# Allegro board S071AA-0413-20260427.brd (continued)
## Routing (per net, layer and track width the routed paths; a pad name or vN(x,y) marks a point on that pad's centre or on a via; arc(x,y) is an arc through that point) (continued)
S1_DCH110: length 194.3
  L18_DIG w0.076: 141.52,222.61 141.52,220.23 v2(141.12,219.83)
  L18_DIG w0.132: 141.52,222.61 142.3,223.39 142.3,235.5 139.59,238.22 139.59,272.89 146.89,280.2 148.28,280.2 181.91,313.83 181.91,392.46 183.15,393.7
S1_DCH111: length 126.1
  L03_DIG w0.132: v2(141.92,222.23) 143.49,223.8 143.49,261.24 184.49,302.24 184.49,329 185.69,330.2
S1_DCH112: length 198.5
  L18_DIG w0.076: 138.29,216.23 139.92,216.23 v2(140.32,215.83)
  L18_DIG w0.132: 167.91,393.7 166.71,392.5 166.71,318.75 130.33,282.37 130.33,236.8 135.88,231.24 135.88,218.64 138.29,216.23
S1_DCH113: length 189.3
  L20_DIG w0.076: v2(141.12,215.83) 140.72,215.43 138.29,215.43
  L20_DIG w0.132: 138.29,215.43 137.24,215.43 134.85,217.82 134.85,222.67 137.25,225.06 137.25,258.53 197.1,318.39 197.1,372.09 198.39,373.38
S1_DCH114: length 173
  L07_DIG w0.076: v2(139.52,217.43) 139.12,217.83 138.42,217.83 138.29,217.96
  L07_DIG w0.132: 138.29,217.96 136.57,219.69 136.57,224.16 137.29,224.88 137.29,228.42 135.44,230.27 135.44,238.17 132.52,241.1 132.52,258.68 160.86,287.02 160.86,312.96 169.15,321.25 169.15,369.54 170.45,370.84
S1_DCH115: length 129.8
  L03_DIG w0.132: v2(138.72,218.23) 137.37,219.58 137.37,274.82 171.79,309.24 171.79,331.54 172.99,332.74
S1_DCH116: length 194.5
  L18_DIG w0.076: 138.29,217.03 139.92,217.03 v2(140.32,216.63)
  L18_DIG w0.132: 170.45,391.16 169.18,389.89 169.18,315.75 132.45,279.01 132.45,235.35 136.61,231.19 136.61,218.71 138.29,217.03
S1_DCH117: length 195.6
  L18_DIG w0.076: v2(140.32,217.43) 139.92,217.83 138.29,217.83
  L18_DIG w0.132: 172.99,393.7 171.72,392.43 171.72,315.01 134.5,277.8 134.5,234.16 137.19,231.48 137.19,218.94 138.29,217.83
S1_DCH118: length 185.8
  L20_DIG w0.076: v2(141.12,216.63) 140.72,216.23 138.29,216.23
  L20_DIG w0.132: 138.29,216.23 137.74,216.23 135.92,218.06 135.92,222.6 137.85,224.53 137.85,255.82 199.67,317.63 199.67,369.58 200.93,370.84
S1_DCH119: length 228.7
  L22_DIG w0.132: v2(138.72,219.03) 138.15,219.6 138.15,241.84 139.37,243.06 139.37,250 155.69,266.32 205.5,266.32 245.57,306.4 245.57,372.31 246.65,373.38
S1_DCH120: length 175.9
  L07_DIG w0.076: v2(139.52,218.23) 139.12,218.63 138.5,218.63 138.29,218.83
  L07_DIG w0.132: 172.99,373.38 171.81,372.2 171.81,321.38 163.27,312.84 163.27,285.99 145.16,267.89 143.81,267.89 141.86,265.94 140.91,265.94 139.89,264.92 139.89,262.62 134.03,256.75 134.03,241.89 135.89,240.03 135.89,230.38 137.87,228.39 137.87,224.37 137.17,223.67 137.17,219.96 138.29,218.83
S1_DCH121: length 182.5
  L07_DIG w0.076: 148.72,206.68 148.72,208.23 v2(148.32,208.63)
  L07_DIG w0.132: 241.57,76.2 237.32,71.95 232.31,71.95 213.15,91.1 213.15,128.86 149.73,192.28 149.73,205.67 148.72,206.68
S1_DCH122: length 207.4
  L22_DIG w0.132: v2(149.12,207.03) 150.44,205.71 150.44,192.13 207.7,134.87 207.7,72.41 205.23,69.94 169.09,69.94 162.83,76.2
S1_DCH123: length 184.1
  L18_DIG w0.076: 148.72,206.68 148.72,209.03 v2(148.32,209.43)
  L18_DIG w0.132: 175.53,78.74 180.31,83.52 202.87,83.52 210.42,91.08 210.42,132.44 151.2,191.66 151.2,204.2 148.72,206.68
S1_DCH124: length 175.7
  L05_DIG w0.076: 149.52,206.68 149.52,207.43 v2(149.12,207.83)
  L05_DIG w0.132: 185.69,78.74 192.97,86.02 206.54,86.02 214.13,93.62 214.13,129.38 149.93,193.59 149.93,206.27 149.52,206.68
S1_DCH125: length 186
  L18_DIG w0.076: v2(147.52,209.43) 147.92,209.03 147.92,206.68
  L18_DIG w0.132: 147.92,206.68 150.15,204.45 150.15,189.94 208.64,131.44 208.64,92.79 202.01,86.16 177.87,86.16 170.45,78.74
S1_DCH126: length 130.2
  L03_DIG w0.132: v2(148.32,207.03) 149.91,205.44 149.91,189.73 194.54,145.11 194.54,97.75 193.31,96.52
S1_DCH127: length 209.1
  L24_DIG w0.076: v2(148.32,207.83) 148.72,207.43 148.72,206.68
  L24_DIG w0.132: 148.72,206.68 149.81,205.59 149.81,193.44 199.31,143.94 199.31,117.14 213.58,102.87 213.58,76.36 205.53,68.3 180.33,68.3 170.45,58.42
S1_DCH128: length 187.4
  L18_DIG w0.076: v2(146.72,209.43) 147.12,209.03 147.12,206.68
  L18_DIG w0.132: 165.37,78.74 175.18,88.55 201.12,88.55 206.18,93.61 206.18,131.35 147.12,190.41 147.12,206.68
S1_DCH129: length 192.1
  L07_DIG w0.076: v2(146.72,208.63) 147.12,208.23 147.12,206.68
  L07_DIG w0.132: 246.65,76.2 240.58,70.13 230.15,70.13 210.19,90.1 210.19,129.09 147.12,192.16 147.12,206.68
S1_DCH130: length 209.4
  L24_DIG w0.076: v2(146.72,207.83) 147.12,207.43 147.12,206.68
  L24_DIG w0.132: 165.37,58.42 178.13,71.18 203.69,71.18 210.39,77.87 210.39,101.54 196.12,115.81 196.12,143.98 147.12,192.98 147.12,206.68
S1_DCH131: length 198.8
  L22_DIG w0.076: v2(147.52,207.83) 147.92,207.43 147.92,206.68
  L22_DIG w0.132: 167.91,76.2 172.46,71.65 204,71.65 205.54,73.18 205.54,133.97 149.88,189.63 149.88,204.72 147.92,206.68
S1_DCH132: length 185.1
  L20_DIG w0.076: 147.92,206.68 147.92,208.23 v2(147.52,208.63)
  L20_DIG w0.132: 172.99,76.2 174.22,77.43 174.22,82.6 180.04,88.43 202.83,88.43 207.75,93.35 207.75,132.13 149.78,190.1 149.78,204.82 147.92,206.68
S1_DCH133: length 258.3
  L24_DIG w0.076: v2(143.52,221.43) 143.92,221.83 143.92,222.61
  L24_DIG w0.132: 256.81,393.7 255.56,392.45 255.56,296.07 243.87,284.38 241.57,284.38 236.91,279.72 236.91,277.42 217.06,257.57 155.03,257.57 145.53,248.07 145.53,235.67 144.53,234.67 144.53,233.68 145.2,233.01 145.2,232.42 144.44,231.66 144.44,230.76 145.53,229.67 145.53,224.8 143.92,223.19 143.92,222.61
S1_DCH134: length 129.8
  L03_DIG w0.132: v2(143.52,222.23) 145.15,223.86 145.15,230.07 144.48,230.74 144.48,231.88 144.82,232.21 144.82,233.16 144.56,233.42 144.56,234.67 145.15,235.26 145.15,256.97 187.05,298.88 187.05,331.56 188.23,332.74
S1_DCH135: length 195.4
  L18_DIG w0.076: 144.72,222.58 144.72,220.23 v2(144.32,219.83)
  L18_DIG w0.132: 144.72,222.58 145.3,223.16 145.3,229.94 144.48,230.76 144.48,231.85 145.08,232.45 145.08,233.17 144.44,233.81 144.44,234.52 145.87,235.94 145.87,263.83 192.09,310.05 192.09,392.48 193.31,393.7
S1_DCH136: length 205.8
  L20_DIG w0.076: v2(144.32,220.63) 144.72,221.03 144.72,222.61
  L20_DIG w0.132: 269.51,330.2 268.24,328.94 268.24,292.37 239.37,263.5 163.6,263.5 147.5,247.39 147.5,229.63 145.87,228 145.87,223.75 144.72,222.61
S1_DCH137: length 147
  L05_DIG w0.076: 144.72,222.61 144.72,221.83 v2(144.32,221.43)
  L05_DIG w0.132: 144.72,222.61 145.24,223.13 145.24,228.21 143.6,229.85 143.6,235.61 145.24,237.25 145.24,270.82 165.61,291.19 165.61,292.34 176.88,303.61 176.88,351.87 178.07,353.06
S1_DCH138: length 128.3
  L03_DIG w0.132: 190.77,330.2 189.53,328.96 189.53,295.34 147.66,253.47 147.66,250.01 146.07,248.42 146.07,238.43 147.45,237.06 147.45,229.78 146.07,228.4 146.07,223.99 v2(144.32,222.23)
S1_DCH139: length 227.9
  L22_DIG w0.076: 145.52,222.61 145.52,221.83 v2(145.12,221.43)
  L22_DIG w0.132: 254.27,370.84 253.17,369.74 253.17,302.07 240.75,289.64 240.75,286.77 235.25,281.28 235.25,279.72 213.69,258.15 156.89,258.15 147.37,248.63 147.37,224.45 145.52,222.61
S1_DCH140: length 254.6
  L24_DIG w0.132: 259.35,391.16 258.05,389.86 258.05,293.6 235.9,271.44 234.48,271.44 230.9,267.87 230.9,266.45 220.22,255.77 156.13,255.77 147.39,247.03 147.39,224.5 v2(145.12,222.23)
S1_DCH141: length 191.3
  L18_DIG w0.076: 143.92,222.58 143.92,220.23 v2(143.52,219.83)
  L18_DIG w0.132: 143.92,222.58 143.92,224.2 143.48,224.64 143.48,261.63 144.37,262.52 144.37,266.44 170.56,292.63 170.56,293.91 189.49,312.84 189.49,389.88 190.77,391.16
S1_DCH142: length 228.2
  L20_DIG w0.076: v2(143.52,220.63) 143.92,221.03 143.92,222.61
  L20_DIG w0.132: 143.92,222.61 145.12,223.81 145.12,230.12 144.4,230.84 144.4,231.66 145.12,232.37 145.12,233.33 144.49,233.96 144.49,234.64 145.12,235.27 145.12,247.85 164.26,266.99 238.48,266.99 265.78,294.29 265.78,351.87 266.97,353.06
S1_DCH143: length 193.5
  L18_DIG w0.076: 143.12,222.58 143.12,220.23 v2(142.72,219.83)
  L18_DIG w0.132: 188.23,393.7 186.96,392.43 186.96,313.56 165.41,292.01 165.41,291.1 142.2,267.9 142.2,244.48 143.12,243.57 143.12,222.58
S1_DCH144: length 223.7
  L20_DIG w0.076: v2(142.72,220.63) 143.12,221.03 143.12,222.61
  L20_DIG w0.132: 264.43,350.52 263.21,349.31 263.21,293.98 238.82,269.59 164.65,269.59 143.56,248.5 143.56,223.05 143.12,222.61
S1_DCH145: length 229.4
  L22_DIG w0.076: 143.12,222.61 143.12,221.83 v2(142.72,221.43)
  L22_DIG w0.132: 251.73,373.38 250.6,372.26 250.6,302.92 237.13,289.45 237.13,286.73 211.81,261.41 156.64,261.41 143.12,247.89 143.12,222.61
S1_DCH146: length 251.1
  L24_DIG w0.132: 254.27,391.16 253.01,389.9 253.01,298.48 235.61,281.08 233.8,281.08 228.94,276.22 228.94,274.66 215.51,261.23 155.93,261.23 143.4,248.7 143.4,224.2 142.72,223.52 v2(142.72,222.23)
S1_DCH147: length 171.9
  L07_DIG w0.076: 142.32,222.61 142.32,221.03 v2(141.92,220.63)
  L07_DIG w0.132: 142.32,222.61 143.52,223.81 143.52,233.61 145.26,235.35 145.26,250.27 176.97,281.98 176.97,284.84 187.01,294.88 187.01,372.16 188.23,373.38
S1_DCH148: length 143
  L05_DIG w0.076: v2(141.92,221.43) 142.32,221.83 142.32,222.61
  L05_DIG w0.132: 175.53,350.52 174.32,349.32 174.32,303.58 162.73,291.99 162.73,290.89 142.32,270.48 142.32,222.61
S1_DCH149: length 184.7
  L20_DIG w0.076: 149.52,206.68 149.52,208.23 v2(149.12,208.63)
  L20_DIG w0.132: 178.07,76.2 179.42,77.55 179.42,82.54 182.91,86.03 205.39,86.03 210.83,91.47 210.83,132.86 150.4,193.29 150.4,205.8 149.52,206.68
S1_DCH150: length 186.4
  L18_DIG w0.076: 149.52,206.68 149.52,209.03 v2(149.12,209.43)
  L18_DIG w0.132: 149.52,206.68 152.85,203.35 152.85,192.45 211.89,133.41 211.89,100.41 229.52,82.79 250.22,82.79 254.27,78.74
S1_DCH151: length 128.1
  L03_DIG w0.132: 195.85,99.06 197.17,100.38 197.17,146.66 150.42,193.4 150.42,206.52 v2(149.92,207.03)
S1_DCH152: length 207.7
  L24_DIG w0.076: v2(149.92,207.83) 150.32,207.43 150.32,206.68
  L24_DIG w0.132: 175.53,58.42 182.86,65.75 207.33,65.75 215.78,74.2 215.78,103.78 201.51,118.05 201.51,143.76 150.32,194.95 150.32,206.68
S1_DCH153: length 168.3
  L07_DIG w0.076: v2(149.92,208.63) 150.32,208.23 150.32,206.68
  L07_DIG w0.132: 236.49,76.2 215.55,97.14 215.55,129.85 150.32,195.08 150.32,206.68
S1_DCH154: length 189.4
  L18_DIG w0.076: 150.32,206.68 150.32,209.03 v2(149.92,209.43)
  L18_DIG w0.132: 259.35,78.74 253.63,84.46 230.75,84.46 213.84,101.37 213.84,134.09 153.69,194.25 153.69,203.31 150.32,206.68
S1_DCH155: length 189.7
  L22_DIG w0.132: v2(150.72,207.03) 151.14,206.61 151.14,193.73 209.33,135.54 209.33,70.08 206.06,66.82 194.09,66.82 185.69,58.42
S1_DCH156: length 176.6
  L05_DIG w0.076: v2(150.72,207.83) 151.12,207.43 151.12,206.68
  L05_DIG w0.132: 151.12,206.68 151.12,196.56 217.44,130.24 217.44,90.31 210.35,83.22 195.24,83.22 190.77,78.74
S1_DCH157: length 184.9
  L20_DIG w0.076: v2(150.72,208.63) 151.12,208.23 151.12,206.68
  L20_DIG w0.132: 183.15,76.2 184.45,77.5 184.45,82.07 185.85,83.47 208.44,83.47 214.25,89.28 214.25,133.5 151.12,196.64 151.12,206.68
S1_DCH158: length 192.5
  L18_DIG w0.076: 151.12,206.68 151.12,209.03 v2(150.72,209.43)
  L18_DIG w0.132: 151.12,206.68 155.34,202.46 155.34,195.11 215.86,134.58 215.86,102.15 231.64,86.38 256.79,86.38 264.43,78.74
S1_DCH159: length 188.9
  L22_DIG w0.076: 151.92,206.68 151.92,207.43 v2(151.52,207.83)
  L22_DIG w0.132: 151.92,206.68 151.92,203.72 152.65,203 152.65,197.29 211.45,138.48 211.45,68.69 207.51,64.74 197.09,64.74 190.77,58.42
S1_DCH160: length 205.5
  L24_DIG w0.132: 180.61,58.42 185.38,63.19 208.79,63.19 218.23,72.64 218.23,104.79 203.96,119.06 203.96,143.46 152.61,194.81 152.61,205.93 v2(151.52,207.03)
S1_DCH161: length 130.6
  L03_DIG w0.132: 198.39,96.52 199.63,97.76 199.63,150.18 153.73,196.08 153.73,205.62 v2(152.32,207.03)
S1_DCH162: length 185.7
  L24_DIG w0.132: 236.49,55.88 220.38,71.99 220.38,105.68 206.11,119.95 206.11,146.39 155.06,197.43 155.06,205.09 v2(153.12,207.03)
S1_DCH163: length 166.1
  L07_DIG w0.076: v2(151.52,208.63) 151.92,208.23 151.92,206.68
  L07_DIG w0.132: 239.03,78.74 218.99,98.78 218.99,131.28 152.68,197.58 152.68,205.92 151.92,206.68
S1_DCH164: length 187.1
  L22_DIG w0.076: v2(152.32,207.83) 152.72,207.43 152.72,206.68
  L22_DIG w0.132: 152.72,206.68 152.72,204.83 153.7,203.85 153.7,198.7 153.93,198.47 213.56,138.84 213.56,67.62 209.08,63.14 200.57,63.14 195.85,58.42
S1_DCH165: length 206.4
  L18_DIG w0.076: v2(151.52,210.23) 151.92,209.83 154.27,209.83
  L18_DIG w0.132: 274.59,78.74 263.29,90.04 233.59,90.04 220.31,103.32 220.31,152.62 163.1,209.83 154.27,209.83
S1_DCH166: length 194.6
  L24_DIG w0.132: v2(153.92,207.83) 156.25,205.5 161.76,205.5 173.98,193.28 173.98,189.14 208.7,154.43 208.7,121.03 222.97,106.75 222.97,73.45 233.74,62.67 239.1,62.67 240.3,61.47 240.3,57.15 241.57,55.88
S1_DCH167: length 185.2
  L22_DIG w0.076: 153.52,206.68 153.52,207.43 v2(153.12,207.83)
  L22_DIG w0.132: 153.52,206.68 153.52,205.71 155.05,204.18 155.05,199.59 215.86,138.78 215.86,67.24 209.03,60.41 202.92,60.41 200.93,58.42
S1_DCH168: length 195.4
  L18_DIG w0.076: v2(151.52,209.43) 151.92,209.03 151.92,206.68
  L18_DIG w0.132: 269.51,78.74 259.85,88.4 232.83,88.4 218.12,103.11 218.12,134.91 155.92,197.11 155.92,202.68 151.92,206.68
S1_DCH169: length 172.2
  L07_DIG w0.076: v2(152.32,209.43) 152.72,209.03 154.27,209.03
  L07_DIG w0.132: 154.27,209.03 158.73,209.03 222.35,145.41 222.35,100.49 244.11,78.74
S1_DCH170: length 193.8
  L22_DIG w0.076: 154.27,208.23 153.52,208.23 v2(153.12,208.63)
  L22_DIG w0.132: 239.03,58.42 236.19,61.25 231.03,61.25 221.88,70.41 221.88,148.34 185.17,185.04 183.01,185.04 159.82,208.23 154.27,208.23
S1_DCH171: length 183.1
  L05_DIG w0.132: 193.31,76.2 197.63,71.88 205.64,71.88 220.55,86.79 220.55,133.8 155.94,198.41 155.94,205.01 v2(153.92,207.03)
S1_DCH172: length 194.3
  L20_DIG w0.076: v2(152.32,208.63) 152.72,208.23 152.72,206.68
  L20_DIG w0.132: 152.72,206.68 153.74,205.66 153.74,199.24 217.41,135.57 217.41,65.43 206.49,54.52 199.75,54.52 198.39,55.88
S1_DCH173: length 192.9
  L20_DIG w0.076: v2(141.12,214.23) 140.72,213.83 138.29,213.83
  L20_DIG w0.132: 138.29,213.83 135.15,213.83 132.44,216.53 132.44,222.56 135.83,225.94 135.83,231.3 134.8,232.33 134.8,262.76 162.97,290.93 162.97,294.25 192.17,323.45 192.17,372.24 193.31,373.38
S1_DCH174: length 248.9
  L24_DIG w0.076: v2(140.32,214.23) 139.92,214.63 138.29,214.63
  L24_DIG w0.132: 239.03,391.16 237.87,390.01 237.87,322.53 189.46,274.11 147.82,274.11 134.14,260.43 134.14,233.75 135.89,232 135.89,215.92 137.18,214.63 138.29,214.63
S1_DCH175: length 189.3
  L20_DIG w0.076: v2(141.12,215.03) 140.72,214.63 138.29,214.63
  L20_DIG w0.132: 138.29,214.63 135.82,214.63 133.25,217.2 133.25,222.19 136.48,225.42 136.48,232.57 135.67,233.38 135.67,261.79 165.44,291.56 165.44,294.05 194.64,323.25 194.64,369.63 195.85,370.84
S1_DCH176: length 249.4
  L24_DIG w0.076: 138.29,215.43 139.92,215.43 v2(140.32,215.03)
  L24_DIG w0.132: 241.57,393.7 240.46,392.59 240.46,321.95 190.56,272.05 150.58,272.05 135.49,256.96 135.49,233.53 136.54,232.48 136.54,216.4 137.52,215.43 138.29,215.43
S1_DCH177: length 222.9
  L22_DIG w0.076: 138.29,215.43 139.12,215.43 v2(139.52,215.03)
  L22_DIG w0.132: 244.11,370.84 242.97,369.71 242.97,320.93 207.4,285.36 206.57,285.36 202.93,281.72 202.93,280.05 190.7,267.82 154.94,267.82 137.35,250.23 137.35,216.38 138.29,215.43
S1_DCH178: length 134.1
  L03_DIG w0.132: v2(138.72,215.03) 136.36,217.39 136.36,232.59 133.47,235.49 133.47,276.72 166.72,309.97 166.72,331.55 167.91,332.74
S1_DCH179: length 176.5
  L07_DIG w0.076: v2(139.52,215.83) 139.12,216.23 138.29,216.23
  L07_DIG w0.132: 138.29,216.23 135.32,219.21 135.32,225.21 135.84,225.74 135.84,228.19 134.7,229.33 134.7,234 128.54,240.16 128.54,260.85 144.96,277.26 146.35,277.26 149.76,280.68 149.76,282.07 157.73,290.03 157.73,315.03 163.96,321.26 163.96,369.43 165.37,370.84
S1_DCH180: length 151.9
  L05_DIG w0.076: v2(138.72,215.83) 138.29,216.26
  L05_DIG w0.132: 138.29,216.26 136.84,217.71 136.84,232.84 135.55,234.13 135.55,273.06 166.67,304.19 166.67,351.82 167.91,353.06
S1_DCH181: length 133.4
  L03_DIG w0.132: v2(138.72,213.43) 135.86,216.29 135.86,231.44 131.96,235.33 131.96,278.42 164.01,310.47 164.01,328.84 165.37,330.2
S1_DCH182: length 224.2
  L22_DIG w0.076: v2(139.52,213.43) 139.12,213.83 138.29,213.83
  L22_DIG w0.132: 239.03,370.84 237.94,369.76 237.94,322.42 187.46,271.93 154.04,271.93 132.88,250.78 132.88,234.33 135.87,231.34 135.87,216.25 138.29,213.83
S1_DCH183: length 151
  L05_DIG w0.076: 138.29,214.66 v2(138.72,214.23)
  L05_DIG w0.132: 138.29,214.66 135.85,217.1 135.85,232.93 134.31,234.47 134.31,274.73 164.01,304.44 164.01,349.17 165.37,350.52
S1_DCH184: length 226.2
  L22_DIG w0.076: 138.29,214.63 139.12,214.63 v2(139.52,214.23)
  L22_DIG w0.132: 241.57,373.38 240.44,372.25 240.44,322.01 187.81,269.38 153.54,269.38 134.39,250.23 134.39,234.9 136.63,232.66 136.63,216.3 138.29,214.63
S1_DCH185: length 128.4
  L03_DIG w0.132: 200.93,330.2 199.72,328.99 199.72,296.04 198.8,295.12 198.8,284.1 153.55,238.85 153.55,224.26 v2(151.52,222.23)
S1_DCH186: length 239.1
  L20_DIG w0.076: v2(149.12,220.63) 149.52,221.03 149.52,222.61
  L20_DIG w0.132: 149.52,222.61 151.19,224.28 162.94,224.28 176.8,238.14 217.36,238.14 271.53,183.97 271.53,129.83 273.24,128.12 273.24,100.53 274.58,99.18
S1_DCH187: length 262.5
  L24_DIG w0.076: 148.72,222.61 148.72,221.83 v2(148.32,221.43)
  L24_DIG w0.132: 266.97,393.7 265.71,392.44 265.71,293.31 264.62,292.23 264.62,283.88 229.48,248.74 159.33,248.74 149.94,239.35 149.94,223.82 148.72,222.61
S1_DCH188: length 142.8
  L05_DIG w0.132: 185.69,350.52 184.43,349.26 184.43,299.56 152.82,267.94 152.82,224.33 v2(150.72,222.23)
S1_DCH189: length 130.1
  L03_DIG w0.132: 193.31,332.74 192.09,331.52 192.09,296.99 190.93,295.83 190.93,290.81 148,247.89 148,224.31 v2(145.92,222.23)
S1_DCH190: length 143.1
  L05_DIG w0.076: 147.12,222.61 147.12,221.83 v2(146.72,221.43)
  L05_DIG w0.132: 180.61,350.52 179.42,349.33 179.42,300.66 147.95,269.19 147.95,223.44 147.12,222.61
S1_DCH191: length 258.3
  L24_DIG w0.076: v2(145.92,221.43) 146.32,221.83 146.32,222.61
  L24_DIG w0.132: 261.89,393.7 260.65,392.46 260.65,291.54 221.98,252.86 157.04,252.86 148.02,243.85 148.02,224.31 146.32,222.61
S1_DCH192: length 152.1
  L07_DIG w0.076: 146.32,222.61 146.32,221.03 v2(145.92,220.63)
  L07_DIG w0.132: 193.31,353.06 192.13,351.88 192.13,310.64 190.82,309.34 190.82,287.02 148.5,244.69 148.5,225.92 146.32,223.74 146.32,222.61
S1_DCH193: length 169.1
  L07_DIG w0.076: v2(145.12,220.63) 145.52,221.03 145.52,222.61
  L07_DIG w0.132: 190.77,370.84 189.54,369.61 189.54,290.04 147.87,248.37 147.87,227 145.52,224.65 145.52,222.61
S1_DCH194: length 192.3
  L18_DIG w0.076: 145.52,222.58 145.52,220.23 v2(145.12,219.83)
  L18_DIG w0.132: 195.85,391.16 194.62,389.93 194.62,309.78 147.38,262.54 147.38,224.44 145.52,222.58
S1_DCH195: length 151
  L07_DIG w0.076: 150.32,222.61 150.32,221.03 v2(149.92,220.63)
  L07_DIG w0.132: 150.32,222.61 152.73,225.02 152.73,237.97 198.41,283.66 198.41,303.36 199.74,304.68 199.74,349.33 200.93,350.52
S1_DCH196: length 171.5
  L18_DIG w0.076: v2(149.12,219.83) 149.52,220.23 149.52,222.58
  L18_DIG w0.132: 149.52,222.58 151.22,224.28 151.22,238.45 240.28,327.52 240.28,351.77 241.57,353.06
S1_DCH197: length 234.8
  L22_DIG w0.076: v2(149.92,221.43) 150.32,221.83 150.32,222.61
  L22_DIG w0.132: 261.89,373.38 260.77,372.26 260.77,289.84 222.44,251.52 160.18,251.52 151.06,242.39 151.06,223.34 150.32,222.61
S1_DCH198: length 219.5
  L24_DIG w0.132: v2(149.92,222.23) 149.92,222.84 150.99,223.91 150.99,236.45 160.94,246.4 232.15,246.4 268.27,282.53 268.27,349.29 269.51,350.52
S1_DCH199: length 168.8
  L18_DIG w0.076: v2(148.32,219.83) 148.72,220.23 148.72,222.58
  L18_DIG w0.132: 239.03,350.52 237.67,349.16 237.67,327.92 180.84,271.1 179.92,271.1 150.59,241.77 150.59,224.45 148.72,222.58
S1_DCH200: length 196.9
  L18_DIG w0.076: 147.92,222.58 147.92,220.23 v2(147.52,219.83)
  L18_DIG w0.132: 203.4,393.59 202.12,392.31 202.12,307.92 177.05,282.85 177.05,282.15 149.96,255.06 149.96,224.63 147.92,222.58
S1_DCH201: length 230.5
  L22_DIG w0.076: v2(149.12,221.43) 149.52,221.83 149.52,222.61
  L22_DIG w0.132: 149.52,222.61 149.52,223.98 150.09,224.55 150.09,244.7 158.46,253.07 218.9,253.07 258.23,292.4 258.23,369.72 259.35,370.84
S1_DCH202: length 131.2
  L03_DIG w0.132: 198.39,332.74 197.16,331.51 197.16,296.64 195.79,295.27 195.79,285.06 151.09,240.36 151.09,225 v2(148.32,222.23)
S1_DCH203: length 153.2
  L07_DIG w0.076: 148.72,222.61 148.72,221.03 v2(148.32,220.63)
  L07_DIG w0.132: 198.39,353.06 197.15,351.82 197.15,305.27 195.71,303.83 195.71,284.96 150.96,240.21 150.96,224.85 148.72,222.61
S1_DCH204: length 144.9
  L05_DIG w0.132: 183.15,353.06 181.93,351.84 181.93,299.66 149.95,267.68 149.95,223.06 v2(149.12,222.23)
S1_DCH205: length 235.8
  L20_DIG w0.076: v2(150.72,220.63) 151.12,221.03 151.12,222.47 151.26,222.61
  L20_DIG w0.132: 272.16,96.38 270.83,97.71 270.83,127.93 269.07,129.69 269.07,182.19 214.28,236.98 177.95,236.98 164.37,223.41 152.06,223.41 151.26,222.61
S1_DCH206: length 236.6
  L22_DIG w0.132: v2(153.12,222.23) 153.71,222.83 153.71,238.26 161.44,245.99 226.73,245.99 264.72,283.97 264.72,292.14 265.9,293.32 265.9,372.31 266.97,373.38
S1_DCH207: length 175.5
  L18_DIG w0.076: v2(151.52,219.83) 151.92,220.23 154.19,220.23 154.27,220.31
  L18_DIG w0.132: 249.19,350.52 247.92,349.25 247.92,325.83 229.06,306.97 229.06,290.98 161.46,223.38 156.3,223.38 155.04,222.11 155.04,221.07 154.27,220.31
S1_DCH208: length 169.7
  L18_DIG w0.076: v2(149.92,219.83) 150.32,220.23 150.32,222.58
  L18_DIG w0.132: 244.11,350.52 242.91,349.32 242.91,327.55 152.62,237.25 152.62,224.88 150.32,222.58
S1_DCH209: length 222.6
  L24_DIG w0.132: 274.59,350.52 273.29,349.22 273.29,292.15 272.59,291.45 272.59,277.62 237.36,242.39 162.8,242.39 153.67,233.27 153.67,223.58 v2(152.32,222.23)
S1_DCH210: length 224
  L24_DIG w0.076: 151.12,222.61 151.12,221.83 v2(150.72,221.43)
  L24_DIG w0.132: 151.12,222.61 152.62,224.11 152.62,234.97 161.64,243.99 233.55,243.99 270.78,281.23 270.78,351.79 272.05,353.06
S1_DCH211: length 233.6
  L22_DIG w0.076: v2(151.52,221.43) 151.92,221.83 151.92,222.57 151.95,222.61
  L22_DIG w0.132: 151.95,222.61 152.71,223.36 152.71,240.69 160.63,248.61 224.6,248.61 262.14,286.15 262.14,292.65 263.26,293.77 263.26,369.67 264.43,370.84
S1_DCH212: length 153.9
  L07_DIG w0.076: v2(151.52,220.63) 151.92,221.03 151.92,222.61
  L07_DIG w0.132: 203.47,353.06 202.3,351.89 202.3,303.64 201.12,302.45 201.12,282.96 153.66,235.5 153.66,224.35 151.92,222.61
S1_DCH213: length 150.2
  L07_DIG w0.076: 154.27,220.31 154.19,220.23 152.72,220.23 v2(152.32,219.83)
  L07_DIG w0.132: 239.03,330.2 237.75,328.92 237.75,310.78 228.86,301.89 228.86,290.68 161.7,223.52 156.58,223.52 155.12,222.06 155.12,221.16 154.27,220.31
S1_DCH214: length 223.1
  L20_DIG w0.076: 154.27,221.04 154.26,221.03 152.72,221.03 v2(152.32,220.63)
  L20_DIG w0.132: 154.27,221.04 154.39,221.04 155.18,221.83 165.5,221.83 176.27,232.59 213.91,232.59 265.36,181.14 265.36,130.73 268.28,127.81 268.28,99.95 269.25,98.98
S1_DCH215: length 146.5
  L05_DIG w0.076: 152.88,222.61 152.72,222.45 152.72,221.83 v2(152.32,221.43)
  L05_DIG w0.132: 152.88,222.61 154.99,224.72 154.99,267.02 186.97,298.99 186.97,351.8 188.23,353.06
S1_DCH216: length 131
  L03_DIG w0.132: 203.47,332.74 202.25,331.52 202.25,295.86 201.34,294.95 201.34,281.92 155.21,235.79 155.21,223.52 v2(153.92,222.23)
S1_DCH217: length 238.5
  L22_DIG w0.076: v2(153.12,221.43) 153.52,221.03 154.27,221.03
  L22_DIG w0.132: 154.27,221.03 155.47,222.23 155.47,236.71 162.18,243.42 229.91,243.42 268.33,281.84 268.33,369.66 269.51,370.84
S1_DCH218: length 227.7
  L24_DIG w0.132: v2(153.92,221.43) 155.99,223.5 155.99,232.67 164.08,240.77 241,240.77 274.82,274.59 274.82,286.19 275.84,287.21 275.84,351.77 277.13,353.06
S1_DCH219: length 173.6
  L18_DIG w0.076: 151.12,222.58 151.12,220.23 v2(150.72,219.83)
  L18_DIG w0.132: 151.12,222.58 153.55,225.01 153.55,236.06 155.23,237.74 156.39,237.74 245.44,326.79 245.44,351.85 246.65,353.06
S1_DCH220: length 145.9
  L05_DIG w0.076: 154.27,221.03 153.52,221.03 v2(153.12,220.63)
  L05_DIG w0.132: 154.27,221.03 156.02,222.78 156.02,256.5 189.5,289.98 189.5,349.25 190.77,350.52
S1_DCH221: length 236.1
  L22_DIG w0.076: 154.27,220.23 153.52,220.23 v2(153.12,219.83)
  L22_DIG w0.132: 272.05,373.38 270.93,372.26 270.93,280.78 222.84,232.7 171.24,232.7 159.28,220.74 155.63,220.74 155.12,220.23 154.27,220.23
S1_DCH222: length 205.7
  L03_DIG w0.132: 249.19,99.06 250.58,100.45 250.58,185.34 207.03,228.9 169.45,228.9 161.93,221.38 156.27,221.38 v2(153.92,219.03)
S1_DCH223: length 214.3
  L03_DIG w0.132: 251.73,96.52 252.93,97.73 252.93,136.41 254.14,137.61 254.14,186.93 209.87,231.2 169.19,231.2 161.76,223.77 157.06,223.77 v2(153.92,220.63)
S1_DCH224: length 258.9
  L24_DIG w0.132: v2(153.92,219.83) 155.58,221.49 157.26,221.49 160.07,224.3 162.19,224.3 168.7,230.81 208.52,230.81 254.9,184.42 254.9,158.14 273.37,139.67 273.37,59.64 274.59,58.42
S1_DCH225: length 217.4
  L20_DIG w0.076: 154.27,219.43 152.72,219.43 v2(152.32,219.03)
  L20_DIG w0.132: 264.31,99.08 263.25,100.14 263.25,127.91 261.41,129.76 261.41,179.77 209.93,231.25 178.07,231.25 167.63,220.81 155.76,220.81 154.38,219.43 154.27,219.43
S1_DCH226: length 222.2
  L05_DIG w0.076: 154.27,219.43 153.52,219.43 v2(153.12,219.03)
  L05_DIG w0.132: 154.27,219.43 155.16,219.43 156.78,221.05 161.83,221.05 172.35,231.58 214.37,231.58 262.42,183.53 262.42,137.48 263.15,136.75 263.15,97.78 261.89,96.52
S1_DCH227: length 180.3
  L18_DIG w0.076: 154.27,219.52 154.18,219.43 151.92,219.43 v2(151.52,219.03)
  L18_DIG w0.132: 251.73,353.06 250.48,351.81 250.48,324.9 231.52,305.94 231.52,290.98 162.12,221.59 156.33,221.59 154.27,219.52
S1_DCH228: length 180.6
  L18_DIG w0.076: 154.27,218.63 151.92,218.63 v2(151.52,218.23)
  L18_DIG w0.132: 254.27,350.52 252.96,349.21 252.96,323.44 234.18,304.66 234.18,291.13 163.62,220.57 156.21,220.57 154.27,218.63
S1_DCH229: length 188
  L18_DIG w0.076: 154.27,217.83 151.92,217.83 v2(151.52,217.43)
  L18_DIG w0.132: 256.81,353.06 255.54,351.79 255.54,310.23 204.61,259.31 204.61,258.39 163.88,217.65 163.08,217.65 162.55,218.18 161.65,218.18 161.07,217.59 160.28,217.59 158.83,219.04 155.48,219.04 154.27,217.83
S1_DCH230: length 156.5
  L07_DIG w0.076: v2(152.32,217.43) 152.72,217.83 154.27,217.83
  L07_DIG w0.132: 154.27,217.83 155.22,217.83 156.48,219.1 159.38,219.1 160.2,219.92 160.89,219.92 161.71,219.1 162.55,219.1 233.78,290.33 233.78,299.25 242.92,308.38 242.92,329.01 244.11,330.2
S1_DCH231: length 155.4
  L07_DIG w0.076: 154.27,218.63 152.72,218.63 v2(152.32,218.23)
  L07_DIG w0.132: 241.57,332.74 240.37,331.54 240.37,309.82 231.3,300.76 231.3,290.49 161.6,220.78 156.85,220.78 154.7,218.63 154.27,218.63
S1_DCH232: length 218.6
  L05_DIG w0.076: 154.27,217.83 153.52,217.83 v2(153.12,217.43)
  L05_DIG w0.132: 154.27,217.83 156.16,217.83 156.54,218.22 157.37,218.22 158.94,216.65 164.74,216.65 165.58,217.49 165.58,219.91 174.49,228.82 215.02,228.82 260.69,183.15 260.69,100.4 259.35,99.06
S1_DCH233: length 239.1
  L22_DIG w0.076: v2(153.12,218.23) 153.52,218.63 154.27,218.63
  L22_DIG w0.132: 274.59,370.84 273.46,369.71 273.46,297.25 274.74,295.96 274.74,279.89 225.42,230.57 173.79,230.57 163.98,220.77 161.13,220.77 158.99,218.63 154.27,218.63
S1_DCH234: length 255.5
  L24_DIG w0.132: 272.05,55.88 270.9,57.03 270.9,133.48 250.31,154.07 250.31,183.65 206.06,227.89 168.71,227.89 161.12,220.3 160.69,220.3 159.42,219.04 154.73,219.04 v2(153.92,218.23)
S1_DCH235: length 128.3
  L03_DIG w0.132: v2(146.72,222.23) 148.51,224.02 148.51,244.9 193.13,289.52 193.13,295.55 194.55,296.97 194.55,328.9 195.85,330.2
S1_DCH236: length 211.6
  L20_DIG w0.076: v2(147.52,220.63) 147.92,221.03 147.92,222.61
  L20_DIG w0.132: 277.13,332.74 275.94,331.55 275.94,290.22 243,257.27 164.84,257.27 150.1,242.53 150.1,224.79 147.92,222.61
S1_DCH237: length 194.3
  L18_DIG w0.076: v2(146.72,219.83) 147.12,220.23 147.12,222.58
  L18_DIG w0.132: 200.93,391.16 199.65,389.88 199.65,308.75 172.91,282.01 171.95,282.01 148.61,258.67 148.61,224.07 147.12,222.58
S1_DCH238: length 151.2
  L07_DIG w0.076: 147.12,222.61 147.12,221.03 v2(146.72,220.63)
  L07_DIG w0.132: 195.85,350.52 194.59,349.26 194.59,296.7 193.55,295.66 193.55,285.51 177.72,269.68 176.12,269.68 175.05,268.61 175.05,267.01 150.17,242.13 150.17,226.76 147.12,223.7 147.12,222.61
S1_DCH239: length 195.6
  L18_DIG w0.076: v2(145.92,219.83) 146.32,220.23 146.32,222.58
  L18_DIG w0.132: 198.39,393.7 197.12,392.43 197.12,308.99 148.01,259.88 148.01,224.27 146.32,222.58
S1_DCH240: length 231.2
  L22_DIG w0.076: v2(147.52,221.43) 147.92,221.83 147.92,222.61
  L22_DIG w0.132: 256.81,373.38 255.7,372.27 255.7,294.95 238.49,277.74 237.53,277.74 215.67,255.87 158.6,255.87 148.44,245.71 148.44,223.12 147.92,222.61
S1_DCH241: length 174.7
  L05_DIG w0.132: 180.61,78.74 190.8,88.93 202.88,88.93 211.16,97.21 211.16,126.24 146.72,190.68 v2(146.72,207.03)
S1_DCH242: length 208.9
  L20_DIG w0.076: v2(146.72,219.03) 146.31,219.44 146.31,222.45
  L20_DIG w0.132: 146.31,222.45 148.66,224.8 148.66,243.31 163.99,258.64 239.85,258.64 273.38,292.17 273.38,328.99 274.59,330.2
S1_DCH243: length 210.6
  L20_DIG w0.076: v2(145.92,219.03) 145.51,219.44 145.51,222.58
  L20_DIG w0.132: 145.51,222.58 148.08,225.14 148.08,245.01 164.38,261.31 239.98,261.31 270.88,292.2 270.88,331.57 272.05,332.74
S1_DCH244: length 257.1
  L24_DIG w0.132: v2(147.52,222.23) 148.67,223.38 148.67,240.94 159.17,251.44 227.07,251.44 262.06,286.44 262.06,293.08 263.1,294.12 263.1,389.83 264.43,391.16
S1_DCH245: length 143.8
  L03_DIG w0.132: K45.2 209.68,174.46 209.68,87.49 200.93,78.74
S1_DCH246: length 163.7
  L03_DIG w0.132: K46.4 K46.5 175.51,217.92 195.05,217.92 235.37,177.6 235.37,97.64 236.49,96.52
S1_DPS11: length 13.9
  L16_DPS w0.076: v2(148.32,216.63) 148.78,217.09 154.27,217.09
  L16_DPS w0.203: 154.27,217.09 154.73,217.09 155.93,218.29 v1(160.44,218.29)
  BOTTOM w0.152: SH15.1 v1(160.44,218.29)
  vias: v1(202.71,292.12) v1(202.71,288.29) v1(202.71,283.21) v1(202.94,279.15) v1(205.52,279.15) v1(205.76,292.12) v1(205.76,288.29) v1(205.76,283.21) v2(144.32,216.63) v2(144.32,215.83) v2(144.32,213.43) v2(144.32,212.63) v2(145.12,216.63) v2(145.12,215.83) v2(145.12,213.43) v2(147.52,216.63) v2(147.52,215.83) v2(147.52,213.43) v2(148.32,215.83)
S1_DPS12: length 15
  L16_DPS w0.076: 140.7,222.61 140.76,222.54 140.76,218.82 140.99,218.59 141.56,218.59 v2(141.92,218.23)
  L16_DPS w0.203: v1(139.86,230.82) 139.86,223.44 140.7,222.61
  BOTTOM w0.152: SH13.1 v1(139.86,230.82)
  vias: v1(172.23,292.12) v1(172.23,288.29) v1(172.23,283.21) v1(172.46,279.15) v1(175.04,279.15) v1(175.28,292.12) v1(175.28,288.29) v1(175.28,283.21) v2(141.92,217.43) v2(141.92,215.03) v2(141.92,214.23) v2(143.52,219.03) v2(144.32,219.03) v2(147.52,219.03) v2(147.52,210.23) v2(149.92,219.03) v2(150.72,219.03) v2(150.72,212.63) v2(150.72,211.83) v2(150.72,211.03) v2(150.72,210.23) v2(151.52,212.63) v2(151.52,211.83) v2(152.32,212.63) v2(152.32,211.83) v2(155.31,213.36) v2(155.31,212.6) v2(155.31,211.84) v2(155.31,211.07)
S1_DPS13: length 11.3
  L09_DPS w0.076: v2(141.92,211.03) 141.51,211.44 141.51,212.02 141.23,212.31 138.29,212.31
  L09_DPS w0.203: v1(132.52,212.67) 137.93,212.67 138.29,212.31
  BOTTOM w0.152: SH9.1 v1(132.52,212.67)
  vias: v1(45.23,292.12) v1(45.23,288.29) v1(45.23,283.21) v1(45.46,279.15) v1(48.04,279.15) v1(48.28,292.12) v1(48.28,288.29) v1(48.28,283.21) v1(61.97,224.69) v1(61.97,209.45) v2(141.92,210.23) v2(145.12,212.63) v2(145.15,211.84)
S1_DPS14: length 13.7
  L11_DPS w0.076: v2(147.38,211.84) 147.13,211.59 147.13,206.68
  L11_DPS w0.203: 147.13,206.68 147.13,206.02 149.14,204.01 v1(149.14,200.22)
  BOTTOM w0.152: v1(149.14,200.22) SH7.1
  vias: v1(146.83,292.12) v1(146.83,288.29) v1(146.83,283.21) v1(147.06,279.15) v1(149.64,279.15) v1(149.88,292.12) v1(149.88,288.29) v1(149.88,283.21) v2(144.32,210.23) v2(145.12,210.23) v2(147.52,212.63)
S1_DPS21: length 14.8
  L11_DPS w0.076: 156.28,212.2 149.9,212.2 148.54,210.85 148.54,210.45 v2(148.32,210.23)
  L11_DPS w0.203: 156.28,212.2 156.64,212.2 157.11,212.67 v1(160.56,212.67)
  BOTTOM w0.152: SH5.1 v1(160.56,212.67)
  vias: v1(123.97,292.12) v1(123.97,288.29) v1(123.97,283.21) v1(124.2,279.15) v1(126.78,279.15) v1(127.02,292.12) v1(127.02,288.29) v1(127.02,283.21)
S1_DPS22: length 20.2
  L11_DPS w0.076: v2(148.32,213.43) 147.93,213.82 147.36,213.82 147.17,214.01 147.17,222.61
  L11_DPS w0.203: v1(145.14,230.92) 145.14,224.72 147.17,222.7 147.17,222.61
  BOTTOM w0.152: SH11.1 v1(145.14,230.92)
  vias: v1(96.03,292.12) v1(96.03,288.29) v1(96.03,283.21) v1(96.26,279.15) v1(98.84,279.15) v1(99.08,292.12) v1(99.08,288.29) v1(99.08,283.21)
S1_DPS23: length 7.5
  L16_DPS w0.203: v1(183.3,204.99) 181.43,203.12 v1(178.87,203.12)
  BOTTOM w0.152: SH3.1 v1(183.3,204.99)
  BOTTOM w0.305: OSC1.4 v1(176.02,204.19)
  vias: v1(235.73,292.12) v1(235.73,288.29) v1(235.73,283.21) v1(235.96,279.15) v1(238.54,279.15) v1(238.78,292.12) v1(238.78,288.29) v1(238.78,283.21) v2(177.6,202.99)
S1_VCC12A_O_REG: length 35.2
  L03_DIG w0.076: 156.28,212.22 148.72,212.22 v2(148.32,212.63)
  L03_DIG w0.132: 156.28,212.22 158.7,212.22 159.75,213.28 169.54,213.28 171.21,211.6 174.59,211.6 K46.3 K46.6
  BOTTOM w0.305: C2.1 K46.6
S1_XOUT: length 30.2
  TOP w0.152: SITE1.Y12 147.52,206.53 148.3,205.75 170.7,205.75 171.69,204.76 174.85,204.76 K45.3
UDBGND: length 147.5
  L14_5V w0.203: 17.24,15.24 UTL1.A02 ; UTL1.A02 18.05,14.43 ; UTL1.A02 18.05,16.05 ; UTL1.A02 18.86,15.24 ; 104.41,410.67 UTL4.B11 ; UTL4.B11 104.41,412.29 ; UTL4.B11 103.6,411.48 ; UTL4.B11 105.22,411.48 ; UTL3.A02 275.4,414.02 ; UTL3.A02 274.59,413.21 ; UTL3.A02 274.59,414.83 ; UTL3.A02 273.78,414.02 ; 165.37,14.43 UTL2.A02 ; UTL2.A02 166.18,15.24 ; UTL2.A02 164.56,15.24 ; UTL2.A02 165.37,16.05 ; UHC230.B2 53.61,353.46 ; UHC230.B2 55.19,353.46 ; UHC230.B2 55.08,351.99 ; UHC230.B2 53.7,351.96 ; UTL1.A10 38.37,16.05 ; UTL1.A10 38.37,14.43 ; UTL1.A10 37.56,15.24 ; UTL1.A10 39.18,15.24 ; UTL2.A08 180.61,16.05 ; UTL2.A08 179.8,15.24 ; UTL2.A08 181.42,15.24 ; UTL2.A08 180.61,14.43 ; 253.46,414.02 UTL3.A10 ; UTL3.A10 254.27,413.21 ; UTL3.A10 254.27,414.83 ; UTL3.A10 255.08,414.02 ; UTL4.A12 101.87,414.83 ; UTL4.A12 101.87,413.21 ; UTL4.A12 101.06,414.02 ; UTL4.A12 102.68,414.02 ; UTL2.B01 162.83,18.59 ; UTL2.B01 162.83,16.97 ; UTL2.B01 163.64,17.78 ; UTL2.B01 162.02,17.78 ; 178.07,16.97 UTL2.B07 ; UTL2.B07 178.07,18.59 ; UTL2.B07 178.88,17.78 ; UTL2.B07 177.26,17.78 ; 32.48,15.24 UTL1.A08 ; UTL1.A08 34.1,15.24 ; UTL1.A08 33.29,16.05 ; UTL1.A08 33.29,14.43 ; 114.57,410.67 UTL4.B07 ; UTL4.B07 114.57,412.29 ; UTL4.B07 115.38,411.48 ; UTL4.B07 113.76,411.48 ; 30.75,16.97 UTL1.B07 ; UTL1.B07 31.56,17.78 ; UTL1.B07 29.94,17.78 ; UTL1.B07 30.75,18.59 ; 244.11,413.21 UTL3.A14 ; UTL3.A14 244.92,414.02 ; UTL3.A14 243.3,414.02 ; UTL3.A14 244.11,414.83 ; UTL2.A10 186.5,15.24 ; UTL2.A10 185.69,16.05 ; UTL2.A10 184.88,15.24 ; UTL2.A10 185.69,14.43 ; UTL2.A14 195.85,16.05 ; UTL2.A14 195.04,15.24 ; UTL2.A14 195.85,14.43 ; UTL2.A14 196.66,15.24 ; UTL2.A12 190.77,16.05 ; UTL2.A12 189.96,15.24 ; UTL2.A12 190.77,14.43 ; UTL2.A12 191.58,15.24 ; UTL4.A14 96.79,414.83 ; UTL4.A14 95.98,414.02 ; UTL4.A14 96.79,413.21 ; UTL4.A14 97.6,414.02 ; 259.35,413.21 UTL3.A08 ; UTL3.A08 259.35,414.83 ; UTL3.A08 260.16,414.02 ; UTL3.A08 258.54,414.02 ; UHC430.B2 55.27,361.96 ; UHC430.B2 53.68,363.55 ; UHC430.B2 53.74,362.16 ; UHC430.B2 55.27,363.69 ; UTL1.A14 48.53,16.05 ; UTL1.A14 49.34,15.24 ; UTL1.A14 47.72,15.24 ; UTL1.A14 48.53,14.43 ; UTL4.A08 112.03,414.83 ; UTL4.A08 112.03,413.21 ; UTL4.A08 111.22,414.02 ; UTL4.A08 112.84,414.02 ; UHC430.D2 53.64,358.56 ; UHC430.D2 55.17,360.09 ; UHC430.D2 53.68,360.05 ; UHC430.D2 55.29,358.43 ; UTL3.B09 256.81,412.29 ; UTL3.B09 257.62,411.48 ; UTL3.B09 256,411.48 ; UTL3.B09 256.81,410.67 ; 42.64,15.24 UTL1.A12 ; UTL1.A12 43.45,14.43 ; UTL1.A12 43.45,16.05 ; UTL1.A12 44.26,15.24 ; UTL3.A12 250,414.02 ; UTL3.A12 249.19,413.21 ; UTL3.A12 249.19,414.83 ; UTL3.A12 248.38,414.02 ; 127.27,413.21 UTL4.A02 ; UTL4.A02 126.46,414.02 ; UTL4.A02 128.08,414.02 ; UTL4.A02 127.27,414.83 ; UTL3.B01 277.94,411.48 ; UTL3.B01 277.13,410.67 ; UTL3.B01 276.32,411.48 ; UTL3.B01 277.13,412.29 ; UTL1.B09 36.64,17.78 ; UTL1.B09 35.83,16.97 ; UTL1.B09 35.83,18.59 ; UTL1.B09 35.02,17.78 ; UTL1.B13 45.99,18.59 ; UTL1.B13 45.99,16.97 ; UTL1.B13 46.8,17.78 ; UTL1.B13 45.18,17.78 ; UTL4.B09 109.49,412.29 ; UTL4.B09 110.3,411.48 ; UTL4.B09 109.49,410.67 ; UTL4.B09 108.68,411.48 ; UHC230.D2 53.64,348.4 ; UHC230.D2 55.17,348.39 ; UHC230.D2 55.19,349.95 ; UHC230.D2 53.68,349.89 ; 14.7,17.78 UTL1.B01 ; UTL1.B01 16.32,17.78 ; UTL1.B01 15.51,18.59 ; UTL1.B01 15.51,16.97 ; 188.23,16.97 UTL2.B11 ; UTL2.B11 189.04,17.78 ; UTL2.B11 187.42,17.78 ; UTL2.B11 188.23,18.59 ; 106.95,413.21 UTL4.A10 ; UTL4.A10 106.95,414.83 ; UTL4.A10 106.14,414.02 ; UTL4.A10 107.76,414.02 ; 99.33,410.67 UTL4.B13 ; UTL4.B13 100.14,411.48 ; UTL4.B13 99.33,412.29 ; UTL4.B13 98.52,411.48 ; UTL2.B13 194.12,17.78 ; UTL2.B13 193.31,18.59 ; UTL2.B13 192.5,17.78 ; UTL2.B13 193.31,16.97 ; 129,411.48 UTL4.B01 ; UTL4.B01 129.81,412.29 ; UTL4.B01 130.62,411.48 ; UTL4.B01 129.81,410.67 ; UTL1.B11 41.72,17.78 ; UTL1.B11 40.91,18.59 ; UTL1.B11 40.91,16.97 ; UTL1.B11 40.1,17.78 ; UTL3.B11 251.73,412.29 ; UTL3.B11 250.92,411.48 ; UTL3.B11 251.73,410.67 ; UTL3.B11 252.54,411.48 ; UTL3.B13 246.65,412.29 ; UTL3.B13 245.84,411.48 ; UTL3.B13 246.65,410.67 ; UTL3.B13 247.46,411.48 ; 261.89,410.67 UTL3.B07 ; UTL3.B07 261.89,412.29 ; UTL3.B07 262.7,411.48 ; UTL3.B07 261.08,411.48 ; UTL2.B09 183.15,18.59 ; UTL2.B09 183.96,17.78 ; UTL2.B09 182.34,17.78 ; UTL2.B09 183.15,16.97
  vias: v1(15.81,284.99) v1(15.81,282.19) v1(16.83,143.26) v1(16.83,140.46) v1(20.57,297.6) v1(22.88,296.69) v1(69.93,18.16) v1(73.16,21.08) v1(75.39,19.56) v1(75.39,18.16) v1(75.39,16.89) v1(75.39,15.49) v1(85.09,131.99) v1(87.39,131.08) v1(96.54,132.78) v1(191.53,133.52) v1(193.84,132.61) v1(263.16,289.13) v1(265.47,288.22) v1(275.91,285.24) v1(275.91,282.45) v1(277.43,133.1) v1(277.43,130.3)
UT1_UP5V: length 547.5
  TOP w0.305: K42.3 156.23,166.88 R42.2 ; R25.2 33.8,230.12 K25.3 ; R29.2 33.8,237.74 K29.3 ; R24.2 104.66,222.5 K24.3 ; K36.3 140.99,143.51 R36.2 ; K40.3 148.61,143.51 R40.2 ; K39.3 125.75,143.76 R39.2 ; KS3.3 50.82,154.18 LRB4.1 ; KS4.3 50.82,161.8 LRB5.1 ; R32.2 104.66,237.74 K32.3 ; R35.2 118.13,143.76 K35.3 ; R3.2 57.42,184.4 K3.3 ; R28.2 104.66,230.12 K28.3 ; R30.2 57.42,237.74 K30.3 ; R2.2 81.04,184.4 K2.3 ; LRB2.1 36.17,132.91 36.62,133.37 KS1.1 ; R17.2 33.8,214.88 K17.3 ; K14.3 81.04,207.26 R14.2 ; KS2.1 54.91,133.37 54.45,132.91 LRB3.1 ; R21.2 33.8,222.5 K21.3 ; K38.3 148.61,166.88 R38.2 ; R5.2 33.8,199.64 K5.3 ; K18.3 57.42,214.88 R18.2 ; K7.3 57.42,207.26 R7.2 ; R13.2 104.66,199.64 K13.3 ; K37.3 125.75,166.88 R37.2 ; K8.3 57.42,199.64 R8.2 ; K15.3 104.66,207.26 R15.2 ; K31.3 81.04,237.74 R31.2 ; R23.2 81.04,222.5 K23.3 ; R46.2 183.02,212.51 182.51,213.03 K46.1 ; R16.2 33.8,184.4 K16.3 ; K1.3 104.66,184.4 R1.2 ; R4.2 33.8,207.26 K4.3 ; K27.3 81.04,230.12 R27.2 ; K34.3 140.99,166.88 R34.2 ; K45.1 183.32,205.92 183.99,205.24 R45.2 ; R20.2 104.66,214.88 K20.3 ; K43.3 133.37,143.76 R43.2 ; R33.2 118.13,166.88 K33.3 ; R10.2 81.04,192.02 K10.3 ; K44.3 156.23,143.51 R44.2 ; K6.3 33.8,192.02 R6.2 ; K12.3 81.04,199.64 R12.2 ; K19.3 81.04,214.88 R19.2 ; R41.2 133.37,166.88 K41.3 ; K22.3 57.42,222.5 R22.2 ; K9.3 57.42,192.02 R9.2 ; R11.2 104.66,192.02 K11.3 ; R26.2 57.42,230.12 K26.3
  L14_5V w0.203: 102.12,185.83 K1.3 ; K1.3 101.01,186.94 ; K1.3 103.24,186.94 ; K1.3 102.12,188.06 ; K25.3 32.38,232.66 ; K25.3 31.26,231.55 ; K25.3 31.26,233.78 ; K25.3 30.14,232.66 ; 121.38,411.48 UTL4.B04 ; UTL4.B04 123,411.48 ; UTL4.B04 122.19,410.67 ; UTL4.B04 122.19,412.29 ; 172.18,15.24 UTL2.A05 ; UTL2.A05 172.99,16.05 ; UTL2.A05 172.99,14.43 ; UTL2.A05 173.8,15.24 ; K21.3 32.38,225.04 ; K21.3 30.14,225.04 ; K21.3 31.26,226.16 ; K21.3 31.26,223.93 ; K33.3 116.7,164.34 ; K33.3 115.59,165.46 ; K33.3 114.47,164.34 ; K33.3 115.59,163.22 ; K46.1 181.42,213.97 ; K46.1 180.48,213.03 ; K46.1 182.36,213.03 ; K46.1 181.42,212.09 ; 180.48,205.92 K45.1 ; K45.1 181.42,206.86 ; K45.1 182.36,205.92 ; K45.1 181.42,204.98 ; K4.3 32.38,209.8 ; K4.3 31.26,210.92 ; K4.3 31.26,208.69 ; K4.3 30.14,209.8 ; 130.83,163.22 K41.3 ; K41.3 130.83,165.46 ; K41.3 131.94,164.34 ; K41.3 129.71,164.34 ; UTL1.A05 25.67,16.05 ; UTL1.A05 24.86,15.24 ; UTL1.A05 25.67,14.43 ; UTL1.A05 26.48,15.24 ; 22.32,17.78 UTL1.B04 ; UTL1.B04 23.13,16.97 ; UTL1.B04 23.13,18.59 ; UTL1.B04 23.94,17.78 ; 123.21,163.22 K37.3 ; K37.3 122.09,164.34 ; K37.3 123.21,165.46 ; K37.3 124.32,164.34 ; 152.57,140.97 K44.3 ; K44.3 154.8,140.97 ; K44.3 153.69,142.09 ; K44.3 153.69,139.85 ; 138.45,163.22 K34.3 ; K34.3 138.45,165.46 ; K34.3 139.56,164.34 ; K34.3 137.33,164.34 ; 102.12,239.17 K32.3 ; K32.3 103.24,240.28 ; K32.3 102.12,241.4 ; K32.3 101.01,240.28 ; 77.38,209.8 K14.3 ; K14.3 78.5,208.69 ; K14.3 78.5,210.92 ; K14.3 79.62,209.8 ; 36.62,133.47 KS1.1 ; KS1.1 35.75,134.34 ; KS1.1 37.5,134.34 ; 102.12,216.31 K20.3 ; K20.3 102.12,218.54 ; K20.3 101.01,217.42 ; K20.3 103.24,217.42 ; 101.01,209.8 K15.3 ; K15.3 102.12,210.92 ; K15.3 103.24,209.8 ; K15.3 102.12,208.69 ; K3.3 54.88,188.06 ; K3.3 53.76,186.94 ; K3.3 54.88,185.83 ; K3.3 56,186.94 ; K10.3 78.5,195.68 ; K10.3 77.38,194.56 ; K10.3 78.5,193.45 ; K10.3 79.62,194.56 ; 146.07,139.85 K40.3 ; K40.3 146.07,142.09 ; K40.3 147.18,140.97 ; K40.3 144.95,140.97 ; K7.3 54.88,210.92 ; K7.3 54.88,208.69 ; K7.3 56,209.8 ; K7.3 53.76,209.8 ; 30.14,186.94 K16.3 ; K16.3 31.26,188.06 ; K16.3 31.26,185.83 ; K16.3 32.38,186.94 ; UTL3.B04 269.51,412.29 ; UTL3.B04 270.32,411.48 ; UTL3.B04 269.51,410.67 ; UTL3.B04 268.7,411.48 ; UTL2.B04 171.26,17.78 ; UTL2.B04 169.64,17.78 ; UTL2.B04 170.45,18.59 ; UTL2.B04 170.45,16.97 ; K13.3 103.24,202.18 ; K13.3 102.12,203.3 ; K13.3 101.01,202.18 ; K13.3 102.12,201.07 ; K5.3 32.38,202.18 ; K5.3 30.14,202.18 ; K5.3 31.26,201.07 ; K5.3 31.26,203.3 ; K31.3 78.5,241.4 ; K31.3 77.38,240.28 ; K31.3 78.5,239.17 ; K31.3 79.62,240.28 ; KS4.3 53.36,160.38 ; KS4.3 53.36,158.14 ; KS4.3 54.47,159.26 ; KS4.3 52.24,159.26 ; K23.3 79.62,225.04 ; K23.3 78.5,226.16 ; K23.3 77.38,225.04 ; K23.3 78.5,223.93 ; 30.14,217.42 K17.3 ; K17.3 31.26,218.54 ; K17.3 31.26,216.31 ; K17.3 32.38,217.42 ; K29.3 32.38,240.28 ; K29.3 31.26,241.4 ; K29.3 30.14,240.28 ; K29.3 31.26,239.17 ; K36.3 138.45,142.09 ; K36.3 139.56,140.97 ; K36.3 138.45,139.85 ; K36.3 137.33,140.97 ; 78.5,216.31 K19.3 ; K19.3 79.62,217.42 ; K19.3 78.5,218.54 ; K19.3 77.38,217.42 ; K30.3 54.88,241.4 ; K30.3 56,240.28 ; K30.3 53.76,240.28 ; K30.3 54.88,239.17 ; 54.88,193.45 K9.3 ; K9.3 54.88,195.68 ; K9.3 56,194.56 ; K9.3 53.76,194.56 ; 101.01,225.04 K24.3 ; K24.3 102.12,223.93 ; K24.3 103.24,225.04 ; K24.3 102.12,226.16 ; K38.3 146.07,165.46 ; K38.3 146.07,163.22 ; K38.3 144.95,164.34 ; K38.3 147.18,164.34 ; 78.5,231.55 K27.3 ; K27.3 78.5,233.78 ; K27.3 77.38,232.66 ; K27.3 79.62,232.66 ; 78.5,201.07 K12.3 ; K12.3 79.62,202.18 ; K12.3 77.38,202.18 ; K12.3 78.5,203.3 ; K22.3 56,225.04 ; K22.3 54.88,226.16 ; K22.3 54.88,223.93 ; K22.3 53.76,225.04 ; 52.24,151.64 KS3.3 ; KS3.3 53.36,150.52 ; KS3.3 53.36,152.76 ; KS3.3 54.47,151.64 ; 53.76,217.42 K18.3 ; K18.3 54.88,216.31 ; K18.3 54.88,218.54 ; K18.3 56,217.42 ; UHC430.C4 51.64,360.34 ; UHC430.C4 51.7,361.87 ; UHC430.C4 50.16,360.33 ; UHC430.C4 50.19,361.79 ; UT_UP5V1.1 94,135.81 ; UT_UP5V1.1 93.06,134.87 ; UT_UP5V1.1 94.94,134.87 ; UT_UP5V1.1 94,133.93 ; K11.3 103.24,194.56 ; K11.3 102.12,195.68 ; K11.3 101.01,194.56 ; K11.3 102.12,193.45 ; 54.88,231.55 K26.3 ; K26.3 53.76,232.66 ; K26.3 56,232.66 ; K26.3 54.88,233.78 ; K42.3 154.8,164.34 ; K42.3 152.57,164.34 ; K42.3 153.69,165.46 ; K42.3 153.69,163.22 ; UTL3.A05 266.97,414.83 ; UTL3.A05 267.78,414.02 ; UTL3.A05 266.16,414.02 ; UTL3.A05 266.97,413.21 ; K39.3 123.21,142.34 ; K39.3 122.09,141.22 ; K39.3 124.32,141.22 ; K39.3 123.21,140.11 ; 54.88,201.07 K8.3 ; K8.3 53.76,202.18 ; K8.3 54.88,203.3 ; K8.3 56,202.18 ; 118.84,414.02 UTL4.A05 ; UTL4.A05 119.65,414.83 ; UTL4.A05 119.65,413.21 ; UTL4.A05 120.46,414.02 ; 129.71,141.22 K43.3 ; K43.3 130.83,142.34 ; K43.3 130.83,140.11 ; K43.3 131.94,141.22 ; K35.3 116.7,141.22 ; K35.3 115.59,142.34 ; K35.3 115.59,140.11 ; K35.3 114.47,141.22 ; KS2.1 55.79,134.34 ; KS2.1 54.91,133.47 ; KS2.1 54.03,134.34 ; K6.3 31.26,195.68 ; K6.3 31.26,193.45 ; K6.3 32.38,194.56 ; K6.3 30.14,194.56 ; K2.3 78.5,188.06 ; K2.3 78.5,185.83 ; K2.3 79.62,186.94 ; K2.3 77.38,186.94 ; 101.01,232.66 K28.3 ; K28.3 102.12,233.78 ; K28.3 103.24,232.66 ; K28.3 102.12,231.55
  vias: v1(20.57,299.3) v1(22.88,299.19) v1(67.07,18.88) v1(67.07,13.63) v1(69.93,19.56) v1(72.16,21.08) v1(85.09,133.69) v1(87.39,133.58) v1(94,132.68) v1(191.53,135.22) v1(193.84,135.11) v1(263.16,290.83) v1(265.47,290.72)
UT1_URW00: length 214.7
  TOP w0.305: LDB2.2 39.88,133.09 39.61,133.37 KS1.9
  L13_CBIT w0.305: UTL1.A01 23.49,7.26 77.67,7.26 81.03,10.62 81.03,92.92 KS1.9
UT1_URW01: length 232.2
  TOP w0.305: LDB3.2 58.17,133.09 57.9,133.37 KS2.9
  L13_CBIT w0.305: UTL1.B02 11.95,23.88 11.95,146.91 29.97,164.93 57.48,164.93 65.28,157.13 65.28,133.42 63.59,131.73 60.51,131.73 KS2.9
UT1_URW02: length 231.6
  TOP w0.305: KS3.1 40.66,154.18 LDB4.2
  L13_CBIT w0.305: UTL1.A03 24.58,11.25 75.96,11.25 78.75,14.04 78.75,84.33 28.99,134.09 28.99,146.28 34.34,151.64 KS3.1
UT1_URW03: length 166.2
  TOP w0.305: KS4.1 40.66,161.8 LDB5.2
  L13_CBIT w0.305: UTL1.B03 13.36,25.01 13.36,143.18 29.44,159.26 KS4.1
UT1_UW14: length 33.1
  L13_CBIT w0.305: UTL1.A13 48.51,12.72 69.62,12.72 71.36,14.46 71.36,15.46 v1(69.93,16.89)
  BOTTOM w0.305: v1(69.93,16.89) 68.76,16.89 68.47,17.18 RB1.2
UT1_UW15: length 26.4
  L13_CBIT w0.305: UTL1.B14 49.92,19.17 64.35,19.17 68.02,15.49 v1(69.93,15.49)
  BOTTOM w0.305: RB2.2 68.59,15.33 68.76,15.49 v1(69.93,15.49)
N18284685: length 3.9
  TOP w0.305: KS2.4 54.22,139.14 54.22,140.11 KB2-4.1
N18284703: length 1.4
  TOP w0.305: LRB2.2 LDB2.1
N18284711: length 4
  TOP w0.305: KS2.3 51.05,137.18 KB2-3.1
N18284713: length 3.9
  TOP w0.305: KB2-6.1 58.59,140.11 58.59,139.14 KS2.6
N18284719: length 4
  TOP w0.305: KS2.7 61.76,137.18 KB2-7.1
N18284723: length 1.4
  TOP w0.305: LDB3.1 LRB3.2
N18284731: length 3.9
  TOP w0.305: KB1-4.1 35.93,140.11 35.93,139.14 KS1.4
N18284735: length 4
  TOP w0.305: KS1.3 32.76,137.18 KB1-3.1
N18284737: length 3.9
  TOP w0.305: KS1.6 40.3,139.14 40.3,140.11 KB1-6.1
N18284739: length 4
  TOP w0.305: KS1.7 43.47,137.18 KB1-7.1
N18284747: length 3.9
  TOP w0.305: KS1.2 34.28,135.61 KB1-2.1
N18284749: length 3.9
  TOP w0.305: KS1.8 41.95,135.61 KB1-8.1
N18284751: length 3.9
  TOP w0.305: KB2-2.1 52.57,135.61 KS2.2
N18284753: length 3.9
  TOP w0.305: KB2-8.1 60.24,135.61 KS2.8
N18285026: length 2.9
  TOP w0.305: LDB4.1 LRB4.2
N18285036: length 2.9
  TOP w0.305: LDB5.1 LRB5.2
N18285067: length 3.6
  TOP w0.305: KS4.4 KB4-4.1
N18285069: length 3.6
  TOP w0.305: KS4.5 KB4-5.1
N18285071: length 3.6
  TOP w0.305: KS4.8 KB4-8.1
N18285089: length 3.6
  TOP w0.305: KS3.8 KB3-8.1
N18285091: length 3.6
  TOP w0.305: KS3.4 KB3-4.1
N18285093: length 3.6
  TOP w0.305: KS3.5 KB3-5.1
N18285182: length 2.6
  TOP w0.152: LRB1.1 95.55,130.98 95.65,130.88 LDB1.1
N22954976: length 2.1
  TOP w0.305: R15.1 LD15.1
N22955016: length 2.1
  TOP w0.305: R16.1 LD16.1
N22955678: length 2.1
  TOP w0.305: R1.1 LD1.1
N22955710: length 2.1
  TOP w0.305: R2.1 LD2.1
N22955758: length 2.1
  TOP w0.305: R3.1 LD3.1
N22955802: length 2.1
  TOP w0.305: R4.1 LD4.1
N22955842: length 2.1
  TOP w0.305: R5.1 LD5.1
N22955878: length 2.1
  TOP w0.305: R6.1 LD6.1
N22955926: length 2.1
  TOP w0.305: R7.1 LD7.1
N22955970: length 2.1
  TOP w0.305: R8.1 LD8.1
N22956024: length 2.1
  TOP w0.305: R9.1 LD9.1
N22956064: length 2.1
  TOP w0.305: R10.1 LD10.1
N22956104: length 2.1
  TOP w0.305: R11.1 LD11.1
N22956144: length 2.1
  TOP w0.305: R12.1 LD12.1
N22956184: length 2.1
  TOP w0.305: R13.1 LD13.1
N22956224: length 2.1
  TOP w0.305: R14.1 LD14.1
N22963164: length 2.1
  TOP w0.305: R19.1 LD19.1
N22963523: length 2.1
  TOP w0.305: R20.1 LD20.1
N22963871: length 2.1
  TOP w0.305: R21.1 LD21.1
N22964216: length 2.1
  TOP w0.305: R22.1 LD22.1
N22964605: length 2.1
  TOP w0.305: R23.1 LD23.1
N22964637: length 2.1
  TOP w0.305: R24.1 LD24.1
N22965490: length 2.1
  TOP w0.305: R17.1 LD17.1
N22965526: length 2.1
  TOP w0.305: R18.1 LD18.1
N22974884: length 2.1
  TOP w0.305: R25.1 LD25.1
N22974900: length 2.1
  TOP w0.305: R26.1 LD26.1
N22974958: length 2.1
  TOP w0.305: R29.1 LD29.1
N22975006: length 2.1
  TOP w0.305: R27.1 LD27.1
N22975038: length 2.1
  TOP w0.305: R28.1 LD28.1
N22975098: length 2.1
  TOP w0.305: R30.1 LD30.1
N22976209: length 2.1
  TOP w0.305: R31.1 LD31.1
N22976245: length 2.1
  TOP w0.305: R32.1 LD32.1
N22984719: length 2.1
  TOP w0.305: R33.1 LD33.1
N22984755: length 2.1
  TOP w0.305: R34.1 LD34.1
N22984791: length 2.1
  TOP w0.305: R35.1 LD35.1
N22984831: length 2.1
  TOP w0.305: LD36.1 R36.1
N22984875: length 2.1
  TOP w0.305: R37.1 LD37.1
N22984899: length 2.1
  TOP w0.305: R38.1 LD38.1
N22984935: length 2.1
  TOP w0.305: R39.1 LD39.1
N22984991: length 2.1
  TOP w0.305: R40.1 LD40.1
N22985097: length 2.1
  TOP w0.305: R41.1 LD41.1
N22985125: length 2.1
  TOP w0.305: R42.1 LD42.1
N22988922: length 2.1
  TOP w0.305: R43.1 LD43.1
N22989162: length 2.1
  TOP w0.305: R44.1 LD44.1
N23040624: length 2.1
  TOP w0.305: LD45.1 R45.1
N23040666: length 2.9
  BOTTOM w0.305: OSC1.3 K45.4
N23043619: length 145.9
  L16_DPS w0.203: v1(186.49,204.99) 228.42,204.99 230.17,206.74 230.17,211.34 230.9,212.08 230.9,287.67 227.07,291.5 224.09,291.5 223.71,291.88 223.71,292.81 223.96,293.06 229.5,293.06 v1(230.14,292.42) v1(232.68,292.42)
  BOTTOM w0.152: SH3.2 v1(186.49,204.99)
N23043647: length 137.5
  L16_DPS w0.203: v1(186.49,203.8) 186.86,203.42 228.16,203.42 230.94,206.2 230.94,211 231.65,211.72 231.65,288.37 v1(227.6,292.42) v1(225.06,292.42)
  BOTTOM w0.152: SH4.2 v1(186.49,203.8)
